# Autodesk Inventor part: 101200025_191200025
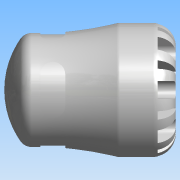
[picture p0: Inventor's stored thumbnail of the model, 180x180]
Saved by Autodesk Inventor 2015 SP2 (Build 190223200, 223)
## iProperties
Created: 2016-12
Part Number: 101200025_191200025
Material: PVC-Piping
Description: PLASSON END PLUG 25 SERIES 1
Document SubType Name: Modeling
Designer: KIM
Mass: 57.8335 g
Surface Area: 121.129 cm^2
Volume: 41.3096 cm^3
Density: 1.4 g/cm^3
Appearance: Smooth - White
Author: KIM
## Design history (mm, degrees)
derived "1012.ipt"
feature "Solid1::1012.ipt"
tag "TaggingFeature1"
body "Solid1"
other parameters: "d1" = 20.16, "d2" = 25, "d3" = 31.25, "d4" = 47, "d6" = 48, "d7" = 52.8, "d8" = 39.95, "d13" = 6.3, "d14" = 6.3, "d15" = 0, "d17" = 360 deg, "d19" = 8 deg, "d20" = 0.5, "d21" = 0.5, "d22" = 8 deg, "d24" = 0, "d26" = 360 deg, "d32" = 4.7, "d33" = 4.7, "d34" = 5.5, "d35" = 8.75, "d36" = 12.348, "d37" = 0, "d42" = 360 deg, "d45" = 7.4375, "d46" = 0.5, "d48" = 0, "d49" = 0.47, "d_" = 25, "E_" = 47, "l_" = 48, "d9" = 7.875, "d11" = 47, "d12" = 31.25
